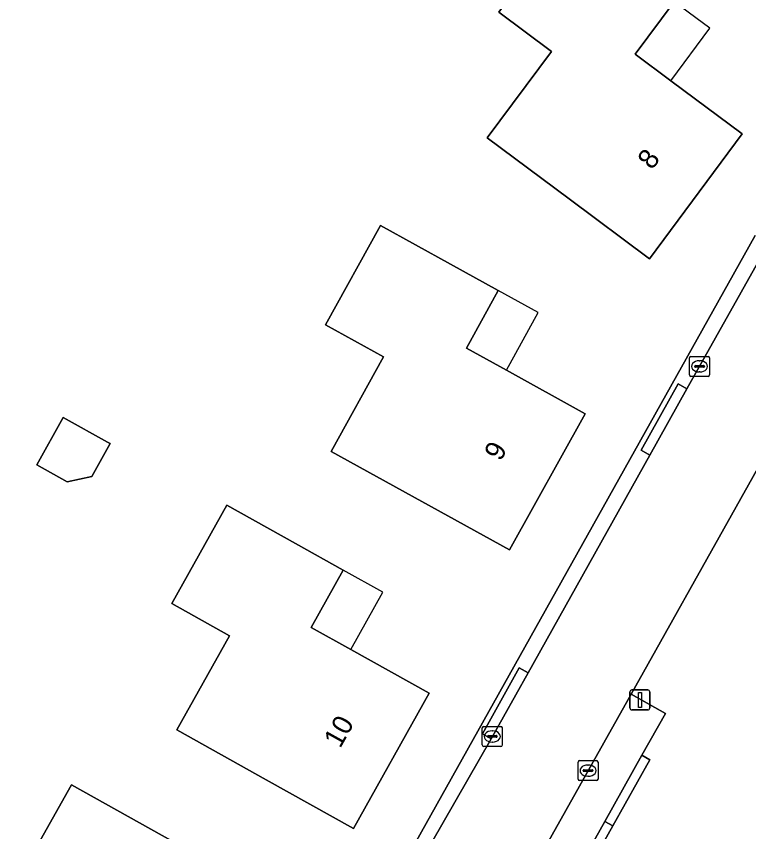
# Model space of a CAD drawing. Extents: x 163266 to 164362, y 381528 to 382286.
# Drawn here: x 163566.78 to 163603.38, y 381629.72 to 381670.48 of the extents above; entities that cross this region are included whole.
import ezdxf

# ---------------------------------------------------------------- set-up
doc = ezdxf.new("R2010")
doc.units = 0
for name, color, linetype in [('IMGEO_Erf', 7, 'Continuous'), ('IMGEO_Kolk', 7, 'Continuous'), ('IMGEO_Lichtmast', 7, 'Continuous'), ('IMGEO_Pand', 7, 'Continuous'), ('IMGEO_Pand_nummerreeks', 7, 'Continuous'), ('IMGEO_Pand_overbouw', 7, 'Continuous'), ('IMGEO_Parkeervlak_open', 7, 'Continuous'), ('IMGEO_Rijbaan_lokaal_open', 7, 'Continuous'), ('IMGEO_Voetpad_open', 7, 'Continuous')]:
    doc.layers.add(name, color=color, linetype=linetype)

msp = doc.modelspace()

# ---------------------------------------------------------------- linework, layer by layer
at = {"layer": 'IMGEO_Erf'}
for points in [[(163603.054, 381664.599), (163598.421, 381658.362), (163594.412, 381661.349), (163590.311, 381664.403), (163593.529, 381668.726), (163590.898, 381670.687), (163594.278, 381675.224), (163597.438, 381672.871), (163599.667, 381671.211), (163597.707, 381668.58), (163599.488, 381667.254)], [(163590.867, 381656.781), (163589.273, 381653.89), (163591.271, 381652.788), (163595.213, 381650.615), (163591.425, 381643.811), (163587.048, 381646.226), (163582.518, 381648.726), (163585.128, 381653.456), (163582.237, 381655.052), (163584.982, 381660.026), (163588.487, 381658.093)], [(163571.34, 381649.185), (163571.462, 381649.117), (163570.547, 381647.48), (163569.319, 381647.214), (163567.806, 381648.059), (163569.126, 381650.421)], [(163581.517, 381639.934), (163583.504, 381638.824), (163587.407, 381636.644), (163583.636, 381629.88), (163579.272, 381632.32), (163574.808, 381634.815), (163577.436, 381639.515), (163574.556, 381641.124), (163577.304, 381646.042), (163580.737, 381644.125), (163583.115, 381642.797)], [(163575.826, 381615.945), (163571.462, 381618.383), (163567.023, 381620.863), (163569.637, 381625.544), (163566.777, 381627.141), (163569.528, 381632.064), (163572.937, 381630.161), (163575.355, 381628.81), (163573.753, 381625.942), (163575.7, 381624.855), (163579.574, 381622.692)]]:
    msp.add_lwpolyline(points, close=True, dxfattribs=at)
for points in [[(163568.157, 381595.963), (163603.714, 381659.518)], [(163608.001, 381655.317), (163597.502, 381636.602), (163599.222, 381635.625), (163598.049, 381633.549), (163598.442, 381633.306), (163596.599, 381630.014), (163582.081, 381604.121), (163581.708, 381604.343), (163581.508, 381603.985)]]:
    msp.add_lwpolyline(points, dxfattribs=at)
at = {"layer": 'IMGEO_Kolk'}
for p, q in [((163600.425, 381652.554), (163600.425, 381653.406)), ((163600.5, 381653.48), (163601.352, 381653.48)), ((163600.913, 381653.26), (163600.938, 381653.26)), ((163601.426, 381653.406), (163601.426, 381652.554)), ((163600.684, 381652.974), (163600.684, 381652.986)), ((163601.122, 381652.937), (163600.724, 381652.937)), ((163600.727, 381653.023), (163601.125, 381653.023)), ((163601.168, 381652.986), (163601.168, 381652.974)), ((163601.352, 381652.48), (163600.5, 381652.48)), ((163600.936, 381652.7), (163600.911, 381652.7)), ((163590.069, 381634.054), (163590.069, 381634.906)), ((163590.144, 381634.98), (163590.996, 381634.98)), ((163591.07, 381634.906), (163591.07, 381634.054)), ((163590.328, 381634.474), (163590.328, 381634.486)), ((163590.371, 381634.523), (163590.769, 381634.523)), ((163590.557, 381634.76), (163590.582, 381634.76)), ((163590.812, 381634.486), (163590.812, 381634.474)), ((163590.766, 381634.437), (163590.368, 381634.437)), ((163590.58, 381634.2), (163590.555, 381634.2)), ((163590.996, 381633.98), (163590.144, 381633.98)), ((163594.928, 381633.273), (163595.78, 381633.273)), ((163594.853, 381632.347), (163594.853, 381633.199)), ((163595.341, 381633.053), (163595.366, 381633.053)), ((163595.854, 381633.199), (163595.854, 381632.347)), ((163595.112, 381632.767), (163595.112, 381632.779)), ((163595.55, 381632.73), (163595.152, 381632.73)), ((163595.155, 381632.816), (163595.553, 381632.816)), ((163595.364, 381632.493), (163595.339, 381632.493)), ((163595.596, 381632.779), (163595.596, 381632.767)), ((163595.78, 381632.273), (163594.928, 381632.273))]:
    msp.add_line(p, q, dxfattribs=at)
for points in [[(163600.425, 381652.554), (163600.425, 381653.406)], [(163600.5, 381653.48), (163601.352, 381653.48)], [(163601.426, 381653.406), (163601.426, 381652.554)], [(163601.352, 381652.48), (163600.5, 381652.48)], [(163590.069, 381634.054), (163590.069, 381634.906)], [(163590.144, 381634.98), (163590.996, 381634.98)], [(163591.07, 381634.906), (163591.07, 381634.054)], [(163590.996, 381633.98), (163590.144, 381633.98)], [(163594.928, 381633.273), (163595.78, 381633.273)], [(163594.853, 381632.347), (163594.853, 381633.199)], [(163595.854, 381633.199), (163595.854, 381632.347)], [(163595.78, 381632.273), (163594.928, 381632.273)]]:
    msp.add_lwpolyline(points, dxfattribs=at)
for centre, radius, start, end in [((163600.502, 381653.404), 0.0765, 91.552, 178.448), ((163600.502, 381653.404), 0.0765, 91.552, 178.448), ((163601.35, 381653.404), 0.0765, 1.552, 88.448), ((163601.35, 381653.404), 0.0765, 1.552, 88.448), ((163600.724, 381652.983), 0.0403, 85.8775, 175.7526), ((163600.721, 381652.973), 0.0366, 178.938, 274.7102), ((163601.125, 381652.98), 0.043, 264.8664, 352.4533), ((163601.129, 381652.985), 0.0386, 1.7309, 96.639), ((163600.502, 381652.556), 0.0765, 181.552, 268.448), ((163600.502, 381652.556), 0.0765, 181.552, 268.448), ((163601.35, 381652.556), 0.0765, 271.552, 358.448), ((163601.35, 381652.556), 0.0765, 271.552, 358.448), ((163590.146, 381634.904), 0.0765, 91.552, 178.448), ((163590.146, 381634.904), 0.0765, 91.552, 178.448), ((163590.994, 381634.904), 0.0765, 1.552, 88.448), ((163590.994, 381634.904), 0.0765, 1.552, 88.448), ((163590.368, 381634.483), 0.0403, 85.8775, 175.7526), ((163590.365, 381634.473), 0.0366, 178.938, 274.7102), ((163590.769, 381634.48), 0.043, 264.8664, 352.4533), ((163590.773, 381634.485), 0.0386, 1.7309, 96.639), ((163590.146, 381634.056), 0.0765, 181.552, 268.448), ((163590.146, 381634.056), 0.0765, 181.552, 268.448), ((163590.994, 381634.056), 0.0765, 271.552, 358.448), ((163590.994, 381634.056), 0.0765, 271.552, 358.448), ((163594.93, 381633.197), 0.0765, 91.552, 178.448), ((163594.93, 381633.197), 0.0765, 91.552, 178.448), ((163595.778, 381633.197), 0.0765, 1.552, 88.448), ((163595.778, 381633.197), 0.0765, 1.552, 88.448), ((163595.557, 381632.778), 0.0386, 1.7309, 96.639), ((163595.152, 381632.776), 0.0403, 85.8775, 175.7526), ((163595.149, 381632.766), 0.0366, 178.938, 274.7102), ((163595.553, 381632.773), 0.043, 264.8664, 352.4533), ((163594.93, 381632.349), 0.0765, 181.552, 268.448), ((163594.93, 381632.349), 0.0765, 181.552, 268.448), ((163595.778, 381632.349), 0.0765, 271.552, 358.448), ((163595.778, 381632.349), 0.0765, 271.552, 358.448)]:
    msp.add_arc(centre, radius, start, end, dxfattribs=at)
for centre, major_axis, ratio, start_param, end_param in [((163600.912, 381652.98), (-0.387, 0.002), 0.722429, 4.712389, 7.853982), ((163600.937, 381652.98), (-0.39, 0.002), 0.717154, 1.570796, 4.712389), ((163590.556, 381634.48), (-0.387, 0.002), 0.722429, 4.712389, 7.853982), ((163590.581, 381634.48), (-0.39, 0.002), 0.717154, 1.570796, 4.712389), ((163595.34, 381632.773), (-0.387, 0.002), 0.722429, 4.712389, 7.853982), ((163595.365, 381632.773), (-0.39, 0.002), 0.717154, 1.570796, 4.712389)]:
    msp.add_ellipse(centre, major_axis=major_axis, ratio=ratio, start_param=start_param, end_param=end_param, dxfattribs=at)
at = {"layer": 'IMGEO_Lichtmast'}
for p, q in [((163597.451, 381635.904), (163597.451, 381636.704)), ((163597.451, 381636.704), (163597.451, 381635.904)), ((163597.551, 381636.804), (163598.341, 381636.804)), ((163598.341, 381636.804), (163597.551, 381636.804)), ((163598.441, 381636.704), (163598.441, 381635.904)), ((163598.441, 381635.904), (163598.441, 381636.704)), ((163598.341, 381635.804), (163597.551, 381635.804)), ((163597.551, 381635.804), (163598.341, 381635.804))]:
    msp.add_line(p, q, dxfattribs=at)
msp.add_lwpolyline([(163597.871, 381636.679), (163598.021, 381636.679), (163598.021, 381635.929), (163597.871, 381635.929), (163597.871, 381636.679)], dxfattribs=at)
for centre, start, end in [((163597.551, 381636.704), 90, 180), ((163597.551, 381636.704), 90, 180), ((163598.341, 381636.704), 0, 90), ((163598.341, 381636.704), 360, 90), ((163597.551, 381635.904), 180, 270), ((163597.551, 381635.904), 180, 270), ((163598.341, 381635.904), 270, 0), ((163598.341, 381635.904), 270, 0)]:
    msp.add_arc(centre, 0.1, start, end, dxfattribs=at)
at = {"layer": 'IMGEO_Pand'}
for points in [[(163599.488, 381667.254), (163597.707, 381668.58), (163599.667, 381671.211), (163597.438, 381672.871), (163594.278, 381675.224), (163590.898, 381670.687), (163593.529, 381668.726), (163590.311, 381664.403), (163594.412, 381661.349), (163598.421, 381658.362), (163603.054, 381664.599)], [(163591.271, 381652.788), (163589.273, 381653.89), (163590.867, 381656.781), (163588.487, 381658.093), (163584.982, 381660.026), (163582.237, 381655.052), (163585.128, 381653.456), (163582.518, 381648.726), (163587.048, 381646.226), (163591.425, 381643.811), (163595.213, 381650.615)], [(163569.319, 381647.214), (163570.547, 381647.48), (163571.462, 381649.117), (163571.34, 381649.185), (163569.126, 381650.421), (163567.806, 381648.059)], [(163583.504, 381638.824), (163581.517, 381639.934), (163583.115, 381642.797), (163580.737, 381644.125), (163577.304, 381646.042), (163574.556, 381641.124), (163577.436, 381639.515), (163574.808, 381634.815), (163579.272, 381632.32), (163583.636, 381629.88), (163587.407, 381636.644)], [(163575.7, 381624.855), (163573.753, 381625.942), (163575.355, 381628.81), (163572.937, 381630.161), (163569.528, 381632.064), (163566.777, 381627.141), (163569.637, 381625.544), (163567.023, 381620.863), (163571.462, 381618.383), (163575.826, 381615.945), (163579.574, 381622.692)]]:
    msp.add_lwpolyline(points, close=True, dxfattribs=at)
at = {"layer": 'IMGEO_Pand_overbouw'}
for points in [[(163601.448, 381669.885), (163599.667, 381671.211), (163597.707, 381668.58), (163599.488, 381667.254)], [(163592.865, 381655.679), (163590.867, 381656.781), (163589.273, 381653.89), (163591.271, 381652.788)], [(163585.102, 381641.687), (163583.115, 381642.797), (163581.517, 381639.934), (163583.504, 381638.824)]]:
    msp.add_lwpolyline(points, close=True, dxfattribs=at)
at = {"layer": 'IMGEO_Parkeervlak_open'}
msp.add_lwpolyline([(163581.508, 381603.985), (163581.708, 381604.343), (163596.189, 381630.224), (163598.049, 381633.549), (163599.222, 381635.625), (163597.502, 381636.602), (163579.965, 381605.349), (163581.284, 381602.447)], dxfattribs=at)
at = {"layer": 'IMGEO_Rijbaan_lokaal_open'}
for points in [[(163606.225, 381661.643), (163604.442, 381659.245), (163600.3, 381651.858), (163598.448, 381648.55), (163592.355, 381637.666), (163590.507, 381634.364), (163586.954, 381628.141), (163586.355, 381627.06), (163583.478, 381621.954), (163582.682, 381620.541), (163581.862, 381619.092), (163576.737, 381609.767), (163574.885, 381606.46), (163569.075, 381596.081)], [(163568.675, 381586.379), (163570.211, 381583.162), (163570.401, 381582.765), (163582.919, 381588.471), (163585.659, 381589.713), (163586.942, 381590.334), (163586.783, 381590.674), (163581.284, 381602.447), (163579.965, 381605.349), (163597.502, 381636.602), (163608.001, 381655.317)]]:
    msp.add_lwpolyline(points, dxfattribs=at)
at = {"layer": 'IMGEO_Voetpad_open'}
for points in [[(163586.954, 381628.141), (163590.507, 381634.364), (163590.071, 381634.608), (163591.919, 381637.91), (163592.355, 381637.666), (163598.448, 381648.55), (163598.012, 381648.794), (163599.865, 381652.102), (163600.3, 381651.858), (163604.442, 381659.245), (163606.225, 381661.643), (163605.872, 381661.996), (163608.556, 381664.608), (163608.858, 381664.28)], [(163603.714, 381659.518), (163568.157, 381595.963)]]:
    msp.add_lwpolyline(points, dxfattribs=at)
for points in [[(163600.3, 381651.858), (163599.865, 381652.102), (163598.012, 381648.794), (163598.448, 381648.55)], [(163592.355, 381637.666), (163591.919, 381637.91), (163590.071, 381634.608), (163590.507, 381634.364)], [(163598.049, 381633.549), (163596.189, 381630.224), (163596.599, 381630.014), (163598.442, 381633.306)], [(163596.189, 381630.224), (163581.708, 381604.343), (163582.081, 381604.121), (163596.599, 381630.014)]]:
    msp.add_lwpolyline(points, close=True, dxfattribs=at)

# ---------------------------------------------------------------- texts
at = {"layer": 'IMGEO_Pand_nummerreeks'}
for s, rotation, p in [('8', 53.3939, (163598.554, 381662.766)), ('9', 60.894, (163590.983, 381648.199)), ('10', 60.8596, (163582.964, 381633.849))]:
    msp.add_text(s, height=1, rotation=rotation, dxfattribs=at).set_placement(p)

doc.saveas('drawing.dxf')
